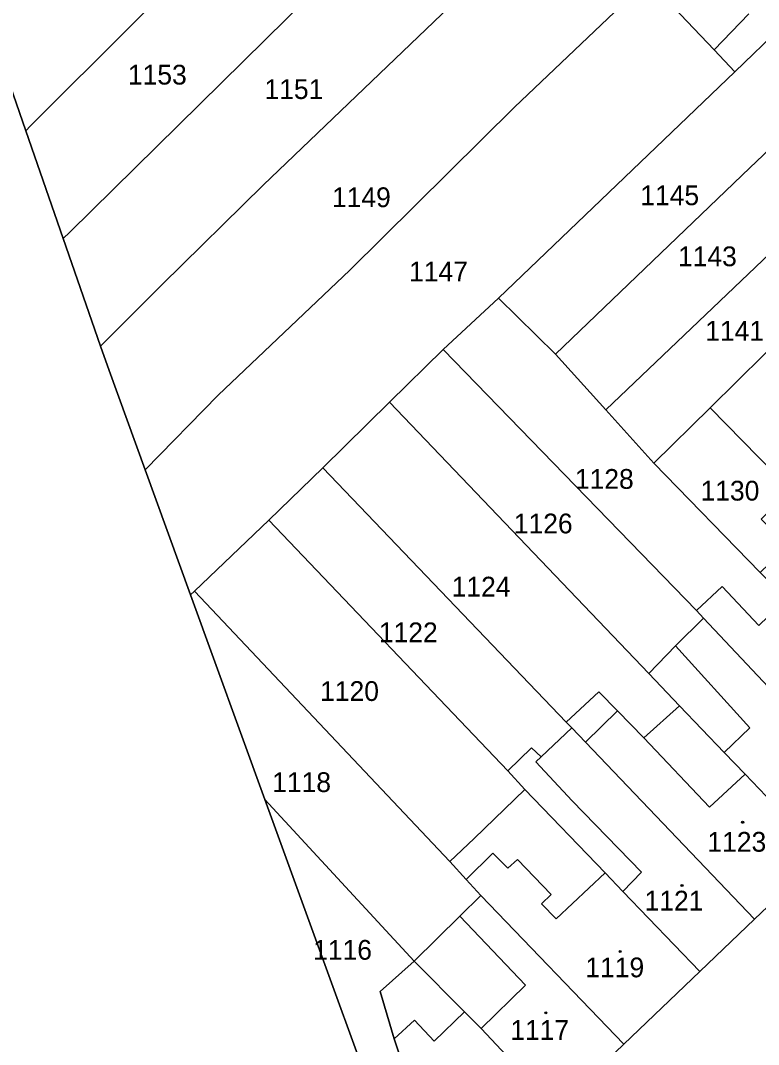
# Model space of a CAD drawing. Extents: x -596233 to -595156, y -1161235 to -1159375.
# Drawn here: x -596094 to -596030.6, y -1160639.3 to -1160551.3 of the extents above; entities that cross this region are included whole.
import ezdxf

# ---------------------------------------------------------------- set-up
doc = ezdxf.new("R2010")
doc.units = 0
for name, color, linetype in [('KN_CAR_KR', 7, 'Continuous'), ('KN_KULTURY', 7, 'Continuous'), ('KN_PARC_CIS_POZ', 7, 'Continuous'), ('KN_PARC_CIS_STAV', 7, 'Continuous'), ('KN_PARC_PLOCHA', 7, 'Continuous'), ('parcely_l', 7, 'Continuous')]:
    doc.layers.add(name, color=color, linetype=linetype)

msp = doc.modelspace()

# ---------------------------------------------------------------- linework, layer by layer
at = {"layer": 'KN_CAR_KR'}
for points in [[(-596031.43, -1160550.69), (-596034.4, -1160553.79)], [(-596037.72, -1160605.05), (-596031.34, -1160612.09)], [(-596045.46, -1160613.32), (-596042.7, -1160610.63)], [(-596031.34, -1160612.09), (-596033.53, -1160614.21)], [(-596040.44, -1160612.95), (-596034.81, -1160618.9), (-596031.74, -1160616.08)], [(-596049.27, -1160614.58), (-596049.72, -1160615)], [(-596049.72, -1160615), (-596046.59, -1160618.37)], [(-596046.59, -1160618.37), (-596040.64, -1160624.51)], [(-596053.43, -1160622.86), (-596055.7, -1160625.14)], [(-596052.13, -1160624.17), (-596053.43, -1160622.86)], [(-596051.31, -1160623.41), (-596052.13, -1160624.17)], [(-596048.4, -1160626.43), (-596051.31, -1160623.41)], [(-596043.77, -1160624.56), (-596047.98, -1160628.51)], [(-596040.64, -1160624.51), (-596042.24, -1160626.15)], [(-596049.23, -1160627.23), (-596048.4, -1160626.43)], [(-596047.98, -1160628.51), (-596049.23, -1160627.23)], [(-596056.27, -1160628.27), (-596050.62, -1160634.23)], [(-596050.62, -1160634.23), (-596054.43, -1160637.94)], [(-596061.9, -1160638.83), (-596060.16, -1160637.22)], [(-596060.16, -1160637.22), (-596058.45, -1160639.02)], [(-596058.45, -1160639.02), (-596055.86, -1160636.5)]]:
    msp.add_lwpolyline(points, dxfattribs=at)
at = {"layer": 'KN_KULTURY'}
for centre, radius in [((-596031.95, -1160620.21), 0.09), ((-596031.95, -1160620.21), 0.0398), ((-596037.16, -1160625.64), 0.09), ((-596037.16, -1160625.64), 0.0398), ((-596042.47, -1160631.32), 0.09), ((-596042.47, -1160631.32), 0.0398), ((-596048.86, -1160636.6), 0.09), ((-596048.86, -1160636.6), 0.0398)]:
    msp.add_circle(centre, radius, dxfattribs=at)
at = {"layer": 'KN_PARC_PLOCHA'}
for points in [[(-596122.76, -1160463.19), (-596116.65, -1160494.33), (-596106.81, -1160522.65), (-596103.73, -1160531.5), (-596101.48, -1160537.98), (-596097.37, -1160549.81), (-596093.57, -1160560.76), (-596090.35, -1160570.03), (-596087.14, -1160579.26), (-596086.4, -1160581.38), (-596083.3, -1160589.91), (-596079.4, -1160600.66), (-596073.02, -1160618.24), (-596059.42, -1160655.68), (-596060.53, -1160656.72), (-596056.91, -1160669.07), (-596058.31, -1160670.5), (-596055.53, -1160677.3), (-596054.27, -1160677.88), (-596054.16, -1160678.25), (-596024.66, -1160758.02)], [(-596047.94, -1160644.86), (-596042.16, -1160639.3), (-596035.64, -1160633.03), (-596030.92, -1160628.54), (-596025.1, -1160623), (-596020.41, -1160618.49), (-596015.68, -1160613.95), (-596010.99, -1160609.45), (-596003.89, -1160602.63), (-595996.79, -1160595.8), (-595990.4, -1160589.65), (-595988.93, -1160588.23), (-595983.43, -1160582.93), (-595971.62, -1160571.62)]]:
    msp.add_lwpolyline(points, dxfattribs=at)
for points in [[(-596061.72, -1160529.19), (-596071.11, -1160538.31), (-596075.54, -1160542.74), (-596093.15, -1160560.34), (-596093.57, -1160560.76), (-596097.37, -1160549.81), (-596069.24, -1160522.08), (-596068.75, -1160521.6), (-596065.4, -1160518.3), (-596061.98, -1160521.63), (-596065.58, -1160525.25)], [(-596048.52, -1160541.57), (-596050.26, -1160543.3), (-596055.82, -1160548.81), (-596073.15, -1160565.44), (-596081.83, -1160573.96), (-596087.14, -1160579.26), (-596090.35, -1160570.03), (-596089.79, -1160569.47), (-596069.26, -1160549.25), (-596062.44, -1160542.56), (-596053.39, -1160533.62), (-596050.02, -1160537.59), (-596051.25, -1160538.91)], [(-596019.38, -1160542.89), (-596028.65, -1160551.85), (-596032.61, -1160555.68), (-596034.4, -1160553.79), (-596039.05, -1160548.9), (-596040.1, -1160547.8), (-596034.18, -1160541.98), (-596026.98, -1160534.97)], [(-596069.26, -1160549.25), (-596089.79, -1160569.47), (-596090.35, -1160570.03), (-596093.57, -1160560.76), (-596093.15, -1160560.34), (-596075.54, -1160542.74), (-596070.88, -1160547.57)], [(-596040.1, -1160547.8), (-596051.55, -1160558.71), (-596065.71, -1160572.73), (-596077.02, -1160583.49), (-596083.3, -1160589.91), (-596086.4, -1160581.38), (-596087.14, -1160579.26), (-596081.83, -1160573.96), (-596073.15, -1160565.44), (-596055.82, -1160548.81), (-596050.26, -1160543.3), (-596048.46, -1160545.11), (-596045.43, -1160542.18)], [(-596032.61, -1160555.68), (-596052.93, -1160575.16), (-596057.69, -1160579.56), (-596062.31, -1160584.1), (-596068.03, -1160589.74), (-596072.68, -1160594.24), (-596079.06, -1160600.34), (-596079.4, -1160600.66), (-596083.3, -1160589.91), (-596077.02, -1160583.49), (-596065.71, -1160572.73), (-596051.55, -1160558.71), (-596040.1, -1160547.8), (-596039.05, -1160548.9), (-596034.4, -1160553.79)], [(-596023.87, -1160556.86), (-596024.28, -1160557.25), (-596024.97, -1160557.9), (-596031.32, -1160563.93), (-596048.02, -1160579.95), (-596052.93, -1160575.16), (-596032.61, -1160555.68), (-596028.65, -1160551.85)], [(-596020.52, -1160562.86), (-596023.49, -1160565.76), (-596024.9, -1160566.93), (-596025.95, -1160567.8), (-596043.71, -1160584.74), (-596048.02, -1160579.95), (-596031.32, -1160563.93), (-596024.97, -1160557.9)], [(-596021.14, -1160571.47), (-596027.79, -1160577.71), (-596034.75, -1160584.57), (-596039.58, -1160589.33), (-596043.71, -1160584.74), (-596025.95, -1160567.8), (-596024.9, -1160566.93)], [(-596048.02, -1160579.95), (-596043.71, -1160584.74), (-596039.58, -1160589.33), (-596030.45, -1160598.74), (-596028.21, -1160601.04), (-596030.57, -1160603.28), (-596033.72, -1160599.95), (-596035.92, -1160602), (-596057.69, -1160579.56), (-596052.93, -1160575.16)], [(-596017.3, -1160588.37), (-596018.4, -1160589.39), (-596021.41, -1160592.65), (-596024.28, -1160595.36), (-596027.8, -1160591.66), (-596034.75, -1160584.57), (-596027.79, -1160577.71)], [(-596035.92, -1160602), (-596035.3, -1160602.66), (-596037.72, -1160605.05), (-596040.02, -1160607.42), (-596062.31, -1160584.1), (-596057.69, -1160579.56)], [(-596040.02, -1160607.42), (-596037.37, -1160610.19), (-596040.44, -1160612.95), (-596042.7, -1160610.63), (-596044.3, -1160609), (-596047.11, -1160611.59), (-596068.03, -1160589.74), (-596062.31, -1160584.1)], [(-596027.8, -1160591.66), (-596030.35, -1160594.15), (-596028.08, -1160596.48), (-596030.45, -1160598.74), (-596039.58, -1160589.33), (-596034.75, -1160584.57)], [(-596047.11, -1160611.59), (-596046.64, -1160612.08), (-596049.27, -1160614.58), (-596050.1, -1160613.82), (-596052.13, -1160615.79), (-596072.68, -1160594.24), (-596068.03, -1160589.74)], [(-596052.13, -1160615.79), (-596050.68, -1160617.4), (-596055.02, -1160621.61), (-596057.11, -1160623.58), (-596079.06, -1160600.34), (-596072.68, -1160594.24)], [(-596028.21, -1160601.04), (-596024.67, -1160604.64), (-596024.13, -1160605.22), (-596023.64, -1160605.72), (-596015.68, -1160613.95), (-596020.41, -1160618.49), (-596035.3, -1160602.66), (-596035.92, -1160602), (-596033.72, -1160599.95), (-596030.57, -1160603.28)], [(-596057.11, -1160623.58), (-596055.7, -1160625.14), (-596054.45, -1160626.51), (-596056.27, -1160628.27), (-596060.19, -1160632.15), (-596073.02, -1160618.24), (-596079.4, -1160600.66), (-596079.06, -1160600.34)], [(-596020.41, -1160618.49), (-596025.1, -1160623), (-596031.74, -1160616.08), (-596033.53, -1160614.21), (-596037.37, -1160610.19), (-596040.02, -1160607.42), (-596037.72, -1160605.05), (-596035.3, -1160602.66)], [(-596037.37, -1160610.19), (-596033.53, -1160614.21), (-596031.74, -1160616.08), (-596025.1, -1160623), (-596030.92, -1160628.54), (-596045.46, -1160613.32), (-596046.64, -1160612.08), (-596047.11, -1160611.59), (-596044.3, -1160609), (-596042.7, -1160610.63), (-596040.44, -1160612.95)], [(-596030.92, -1160628.54), (-596035.64, -1160633.03), (-596042.24, -1160626.15), (-596043.77, -1160624.56), (-596050.68, -1160617.4), (-596052.13, -1160615.79), (-596050.1, -1160613.82), (-596049.27, -1160614.58), (-596046.64, -1160612.08), (-596045.46, -1160613.32)], [(-596035.64, -1160633.03), (-596042.16, -1160639.3), (-596054.45, -1160626.51), (-596055.7, -1160625.14), (-596057.11, -1160623.58), (-596055.02, -1160621.61), (-596050.68, -1160617.4), (-596043.77, -1160624.56), (-596042.24, -1160626.15)], [(-596060.19, -1160632.15), (-596063.1, -1160634.75), (-596061.9, -1160638.83), (-596060.8, -1160642.12), (-596062.18, -1160642.67), (-596061.36, -1160645.21), (-596059.93, -1160644.74), (-596056.98, -1160653.57), (-596059.42, -1160655.68), (-596073.02, -1160618.24)], [(-596042.16, -1160639.3), (-596047.94, -1160644.86), (-596054.43, -1160637.94), (-596055.86, -1160636.5), (-596060.19, -1160632.15), (-596056.27, -1160628.27), (-596054.45, -1160626.51)], [(-596047.94, -1160644.86), (-596056.98, -1160653.57), (-596059.93, -1160644.74), (-596061.36, -1160645.21), (-596062.18, -1160642.67), (-596060.8, -1160642.12), (-596061.9, -1160638.83), (-596063.1, -1160634.75), (-596060.19, -1160632.15), (-596055.86, -1160636.5), (-596054.43, -1160637.94)]]:
    msp.add_lwpolyline(points, close=True, dxfattribs=at)
at = {"layer": 'parcely_l'}
for points in [[(-596075.54, -1160542.74), (-596093.15, -1160560.34), (-596093.57, -1160560.76)], [(-596050.26, -1160543.3), (-596055.82, -1160548.81), (-596073.15, -1160565.44), (-596081.83, -1160573.96), (-596087.14, -1160579.26)], [(-596040.1, -1160547.8), (-596051.55, -1160558.71), (-596065.71, -1160572.73), (-596077.02, -1160583.49), (-596083.3, -1160589.91)], [(-596032.61, -1160555.68), (-596034.4, -1160553.79), (-596039.05, -1160548.9), (-596040.1, -1160547.8)], [(-596093.57, -1160560.76), (-596097.37, -1160549.81)], [(-596090.35, -1160570.03), (-596089.79, -1160569.47), (-596069.26, -1160549.25)], [(-596032.61, -1160555.68), (-596028.65, -1160551.85)], [(-596052.93, -1160575.16), (-596032.61, -1160555.68)], [(-596024.97, -1160557.9), (-596031.32, -1160563.93), (-596048.02, -1160579.95)], [(-596093.57, -1160560.76), (-596090.35, -1160570.03)], [(-596024.9, -1160566.93), (-596025.95, -1160567.8), (-596043.71, -1160584.74)], [(-596090.35, -1160570.03), (-596087.14, -1160579.26)], [(-596057.69, -1160579.56), (-596052.93, -1160575.16)], [(-596048.02, -1160579.95), (-596052.93, -1160575.16)], [(-596034.75, -1160584.57), (-596027.79, -1160577.71)], [(-596087.14, -1160579.26), (-596086.4, -1160581.38), (-596083.3, -1160589.91)], [(-596062.31, -1160584.1), (-596057.69, -1160579.56)], [(-596035.92, -1160602), (-596057.69, -1160579.56)], [(-596048.02, -1160579.95), (-596043.71, -1160584.74)], [(-596068.03, -1160589.74), (-596062.31, -1160584.1)], [(-596040.02, -1160607.42), (-596062.31, -1160584.1)], [(-596043.71, -1160584.74), (-596039.58, -1160589.33)], [(-596034.75, -1160584.57), (-596039.58, -1160589.33)], [(-596027.8, -1160591.66), (-596034.75, -1160584.57)], [(-596039.58, -1160589.33), (-596030.45, -1160598.74)], [(-596083.3, -1160589.91), (-596079.4, -1160600.66)], [(-596068.03, -1160589.74), (-596072.68, -1160594.24)], [(-596047.11, -1160611.59), (-596068.03, -1160589.74)], [(-596079.06, -1160600.34), (-596072.68, -1160594.24)], [(-596072.68, -1160594.24), (-596052.13, -1160615.79)], [(-596028.21, -1160601.04), (-596030.57, -1160603.28), (-596033.72, -1160599.95), (-596035.92, -1160602)], [(-596079.4, -1160600.66), (-596079.06, -1160600.34)], [(-596073.02, -1160618.24), (-596079.4, -1160600.66)], [(-596079.06, -1160600.34), (-596057.11, -1160623.58)], [(-596035.92, -1160602), (-596035.3, -1160602.66)], [(-596040.02, -1160607.42), (-596037.72, -1160605.05), (-596035.3, -1160602.66)], [(-596035.3, -1160602.66), (-596020.41, -1160618.49)], [(-596037.37, -1160610.19), (-596040.02, -1160607.42)], [(-596037.37, -1160610.19), (-596040.44, -1160612.95), (-596042.7, -1160610.63), (-596044.3, -1160609), (-596047.11, -1160611.59)], [(-596025.1, -1160623), (-596031.74, -1160616.08), (-596033.53, -1160614.21), (-596037.37, -1160610.19)], [(-596046.64, -1160612.08), (-596047.11, -1160611.59)], [(-596052.13, -1160615.79), (-596050.1, -1160613.82), (-596049.27, -1160614.58), (-596046.64, -1160612.08)], [(-596046.64, -1160612.08), (-596045.46, -1160613.32), (-596030.92, -1160628.54)], [(-596052.13, -1160615.79), (-596050.68, -1160617.4)], [(-596050.68, -1160617.4), (-596055.02, -1160621.61), (-596057.11, -1160623.58)], [(-596050.68, -1160617.4), (-596043.77, -1160624.56), (-596042.24, -1160626.15), (-596035.64, -1160633.03)], [(-596060.19, -1160632.15), (-596073.02, -1160618.24)], [(-596073.02, -1160618.24), (-596059.42, -1160655.68)], [(-596030.92, -1160628.54), (-596025.1, -1160623)], [(-596057.11, -1160623.58), (-596055.7, -1160625.14), (-596054.45, -1160626.51)], [(-596054.45, -1160626.51), (-596056.27, -1160628.27), (-596060.19, -1160632.15)], [(-596042.16, -1160639.3), (-596054.45, -1160626.51)], [(-596030.92, -1160628.54), (-596035.64, -1160633.03)], [(-596056.98, -1160653.57), (-596059.93, -1160644.74), (-596061.36, -1160645.21), (-596062.18, -1160642.67), (-596060.8, -1160642.12), (-596061.9, -1160638.83), (-596063.1, -1160634.75), (-596060.19, -1160632.15)], [(-596060.19, -1160632.15), (-596055.86, -1160636.5), (-596054.43, -1160637.94), (-596047.94, -1160644.86)], [(-596035.64, -1160633.03), (-596042.16, -1160639.3)], [(-596047.94, -1160644.86), (-596042.16, -1160639.3)]]:
    msp.add_lwpolyline(points, dxfattribs=at)

# ---------------------------------------------------------------- texts
at = {"layer": 'KN_PARC_CIS_POZ'}
for s, p in [('1153', (-596084.7866, -1160556.78)), ('1151', (-596073.0466, -1160558.02)), ('1149', (-596067.2466, -1160567.32)), ('1145', (-596040.7466, -1160567.15)), ('1143', (-596037.5066, -1160572.4)), ('1147', (-596060.6166, -1160573.7)), ('1141', (-596035.1666, -1160578.8)), ('1128', (-596046.3666, -1160591.54)), ('1130', (-596035.5666, -1160592.55)), ('1126', (-596051.6166, -1160595.37)), ('1124', (-596056.9566, -1160600.8)), ('1122', (-596063.2166, -1160604.73)), ('1120', (-596068.2666, -1160609.78)), ('1118', (-596072.3866, -1160617.61)), ('1116', (-596068.8666, -1160632.03))]:
    msp.add_text(s, height=1.7, dxfattribs=at).set_placement(p)
at = {"layer": 'KN_PARC_CIS_STAV'}
for s, p in [('1123', (-596034.9766, -1160622.74)), ('1121', (-596040.3766, -1160627.8)), ('1119', (-596045.4666, -1160633.54)), ('1117', (-596051.9166, -1160638.92))]:
    msp.add_text(s, height=1.7, dxfattribs=at).set_placement(p)

doc.saveas('drawing.dxf')
